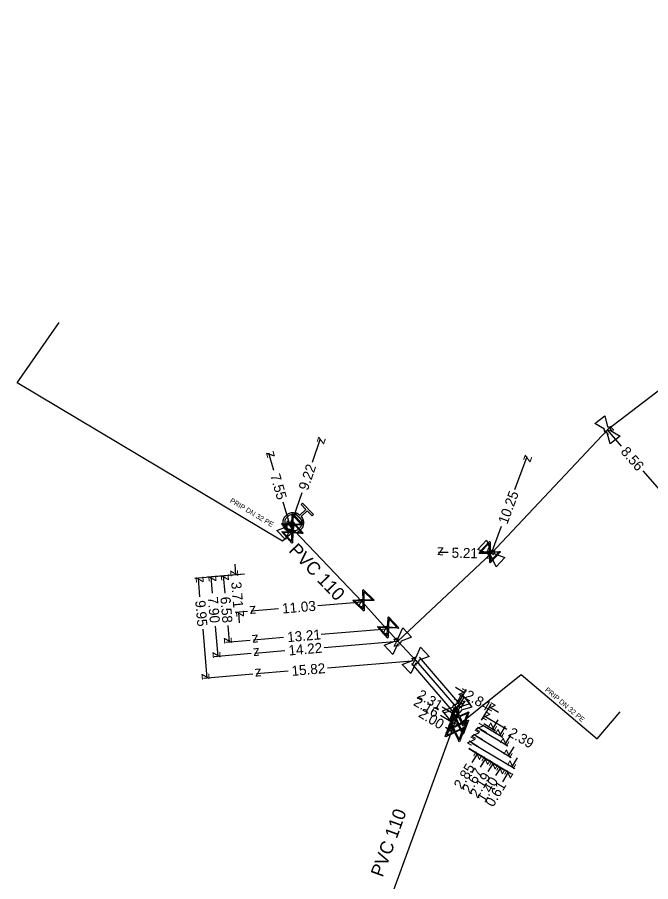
# Model space of a CAD drawing. Extents: x -638315 to -636370, y -1116147 to -1115110.
# Drawn here: x -637146.8 to -637084.1, y -1115729.6 to -1115644 of the extents above; entities that cross this region are included whole.
import ezdxf

# ---------------------------------------------------------------- set-up
doc = ezdxf.new("R2010")
doc.units = 0
for name, color, linetype in [('Default', 7, 'Continuous'), ('VP Chránička', 7, 'Continuous'), ('VP Hydrant', 7, 'Continuous'), ('VP Kótování', 7, 'Continuous'), ('VP Lomový bod', 7, 'Continuous'), ('VP Popis přípojky', 7, 'Continuous'), ('VP Přípojka', 7, 'Continuous'), ('VP Řad', 7, 'Continuous'), ('VP Řad - popis', 7, 'Continuous'), ('VP Šoupě', 7, 'Continuous')]:
    doc.layers.add(name, color=color, linetype=linetype)

msp = doc.modelspace()

# ---------------------------------------------------------------- linework, layer by layer
at = {"layer": 'Default'}
for points in [[(-637088.361, -1115684.546), (-637088.309, -1115684.55), (-637088.26, -1115684.571), (-637088.181, -1115684.606), (-637088.131, -1115684.671), (-637088.082, -1115684.736), (-637088.07, -1115684.819), (-637088.063, -1115684.873), (-637088.074, -1115684.925)], [(-637088.398, -1115685.172), (-637088.451, -1115685.169), (-637088.501, -1115685.148), (-637088.579, -1115685.115), (-637088.628, -1115685.05), (-637088.678, -1115684.985), (-637088.69, -1115684.898), (-637088.698, -1115684.846), (-637088.686, -1115684.794)], [(-637118.695, -1115693.44), (-637118.469, -1115693.72), (-637118.479, -1115694.086), (-637118.49, -1115694.499), (-637118.791, -1115694.786), (-637119.091, -1115695.071), (-637119.504, -1115695.061), (-637119.918, -1115695.05), (-637120.205, -1115694.749), (-637120.489, -1115694.451), (-637120.48, -1115694.037), (-637120.471, -1115693.624), (-637120.171, -1115693.338), (-637119.87, -1115693.051), (-637119.457, -1115693.059), (-637119.09, -1115693.065), (-637118.822, -1115693.307)], [(-637118.891, -1115693.497), (-637119.125, -1115693.252), (-637119.46, -1115693.244), (-637119.796, -1115693.236), (-637120.04, -1115693.47), (-637120.285, -1115693.703), (-637120.293, -1115694.038), (-637120.301, -1115694.374), (-637120.068, -1115694.618), (-637119.836, -1115694.861), (-637119.5, -1115694.87), (-637119.164, -1115694.879), (-637118.919, -1115694.646), (-637118.674, -1115694.413), (-637118.666, -1115694.077), (-637118.658, -1115693.742), (-637118.891, -1115693.497)], [(-637119.786, -1115694.043), (-637119.692, -1115694.043), (-637119.602, -1115694.091), (-637119.512, -1115694.14), (-637119.462, -1115694.23), (-637119.411, -1115694.32), (-637119.411, -1115694.418), (-637119.411, -1115694.516), (-637119.46, -1115694.605), (-637119.51, -1115694.694), (-637119.599, -1115694.744), (-637119.689, -1115694.793), (-637119.786, -1115694.793), (-637119.883, -1115694.793), (-637119.973, -1115694.744), (-637120.062, -1115694.694), (-637120.112, -1115694.605), (-637120.161, -1115694.516), (-637120.161, -1115694.418), (-637120.161, -1115694.32), (-637120.111, -1115694.23), (-637120.06, -1115694.14), (-637119.971, -1115694.091), (-637119.881, -1115694.043), (-637119.786, -1115694.043)], [(-637119.786, -1115694.09), (-637119.869, -1115694.09), (-637119.948, -1115694.132), (-637120.026, -1115694.174), (-637120.07, -1115694.253), (-637120.114, -1115694.332), (-637120.114, -1115694.418), (-637120.114, -1115694.504), (-637120.071, -1115694.582), (-637120.028, -1115694.659), (-637119.95, -1115694.703), (-637119.871, -1115694.746), (-637119.786, -1115694.746), (-637119.701, -1115694.746), (-637119.622, -1115694.703), (-637119.544, -1115694.659), (-637119.501, -1115694.582), (-637119.458, -1115694.504), (-637119.458, -1115694.418), (-637119.458, -1115694.332), (-637119.502, -1115694.253), (-637119.547, -1115694.174), (-637119.625, -1115694.132), (-637119.704, -1115694.09), (-637119.786, -1115694.09)], [(-637120.098, -1115694.434), (-637120.101, -1115694.381), (-637120.085, -1115694.329), (-637120.061, -1115694.249), (-637120.001, -1115694.192), (-637119.942, -1115694.136), (-637119.858, -1115694.114), (-637119.807, -1115694.101), (-637119.754, -1115694.106)], [(-637119.472, -1115694.402), (-637119.47, -1115694.454), (-637119.485, -1115694.506), (-637119.511, -1115694.588), (-637119.57, -1115694.644), (-637119.629, -1115694.701), (-637119.711, -1115694.721), (-637119.764, -1115694.735), (-637119.816, -1115694.729)], [(-637099.846, -1115697.423), (-637099.898, -1115697.429), (-637099.951, -1115697.416), (-637100.033, -1115697.396), (-637100.093, -1115697.34), (-637100.153, -1115697.284), (-637100.178, -1115697.201), (-637100.195, -1115697.151), (-637100.192, -1115697.098)], [(-637099.912, -1115696.8), (-637099.861, -1115696.795), (-637099.808, -1115696.807), (-637099.725, -1115696.828), (-637099.665, -1115696.884), (-637099.606, -1115696.94), (-637099.581, -1115697.021), (-637099.564, -1115697.073), (-637099.567, -1115697.126)], [(-637109.443, -1115705.802), (-637109.445, -1115705.749), (-637109.428, -1115705.697), (-637109.403, -1115705.617), (-637109.343, -1115705.561), (-637109.284, -1115705.505), (-637109.199, -1115705.485), (-637109.148, -1115705.472), (-637109.095, -1115705.478)], [(-637108.816, -1115705.777), (-637108.815, -1115705.829), (-637108.83, -1115705.881), (-637108.857, -1115705.962), (-637108.917, -1115706.018), (-637108.977, -1115706.074), (-637109.059, -1115706.094), (-637109.112, -1115706.106), (-637109.165, -1115706.1)], [(-637107.673, -1115707.702), (-637107.675, -1115707.649), (-637107.658, -1115707.597), (-637107.633, -1115707.517), (-637107.573, -1115707.461), (-637107.514, -1115707.405), (-637107.429, -1115707.385), (-637107.378, -1115707.372), (-637107.325, -1115707.378)], [(-637107.046, -1115707.677), (-637107.045, -1115707.729), (-637107.06, -1115707.781), (-637107.087, -1115707.862), (-637107.147, -1115707.918), (-637107.207, -1115707.974), (-637107.289, -1115707.994), (-637107.342, -1115708.006), (-637107.395, -1115708)], [(-637103.683, -1115712.339), (-637103.683, -1115712.286), (-637103.664, -1115712.235), (-637103.636, -1115712.156), (-637103.574, -1115712.102), (-637103.512, -1115712.049), (-637103.427, -1115712.032), (-637103.375, -1115712.022), (-637103.322, -1115712.03)], [(-637103.481, -1115712.583), (-637103.479, -1115712.53), (-637103.457, -1115712.48), (-637103.424, -1115712.402), (-637103.36, -1115712.352), (-637103.295, -1115712.303), (-637103.209, -1115712.29), (-637103.156, -1115712.282), (-637103.105, -1115712.294)], [(-637103.056, -1115712.34), (-637103.057, -1115712.392), (-637103.074, -1115712.443), (-637103.105, -1115712.524), (-637103.167, -1115712.577), (-637103.229, -1115712.63), (-637103.312, -1115712.646), (-637103.365, -1115712.657), (-637103.417, -1115712.649)], [(-637102.856, -1115712.618), (-637102.859, -1115712.67), (-637102.879, -1115712.719), (-637102.914, -1115712.798), (-637102.979, -1115712.848), (-637103.044, -1115712.898), (-637103.127, -1115712.91), (-637103.181, -1115712.917), (-637103.233, -1115712.906)]]:
    msp.add_open_spline(points, degree=3, dxfattribs=at)
at = {"layer": 'VP Chránička'}
for points in [[(-637102.99, -1115712.014), (-637106.98, -1115707.364)], [(-637103.749, -1115712.665), (-637107.739, -1115708.015)]]:
    msp.add_lwpolyline(points, dxfattribs=at)
at = {"layer": 'VP Hydrant'}
msp.add_lwpolyline([(-637118.822, -1115693.307), (-637118.228, -1115692.741), (-637118.704, -1115692.242), (-637118.571, -1115692.115), (-637117.493, -1115693.246), (-637117.626, -1115693.373), (-637118.102, -1115692.874), (-637118.695, -1115693.44)], dxfattribs=at)
at = {"layer": 'VP Kótování'}
for points in [[(-637086.987, -1115686.468), (-637088.38, -1115684.86)], [(-637117.587, -1115688.07), (-637116.77, -1115685.71)], [(-637121.397, -1115688.895), (-637121.9, -1115687.17)], [(-637097.535, -1115690.763), (-637096.33, -1115687.5)], [(-637084.864, -1115688.918), (-637082.776, -1115691.328)], [(-637118.637, -1115691.101), (-637119.786, -1115694.418)], [(-637120.498, -1115691.977), (-637119.786, -1115694.418)], [(-637098.889, -1115694.431), (-637099.879, -1115697.112)], [(-637104.156, -1115697.02), (-637105.09, -1115697)], [(-637101.124, -1115697.085), (-637099.879, -1115697.112)], [(-637125.281, -1115698.178), (-637125.193, -1115699.224)], [(-637124.319, -1115699.15), (-637129.224, -1115699.566)], [(-637128.717, -1115701.395), (-637128.875, -1115699.537)], [(-637124.319, -1115699.15), (-637127.968, -1115699.46)], [(-637127.482, -1115701.044), (-637127.619, -1115699.43)], [(-637124.319, -1115699.15), (-637126.728, -1115699.354)], [(-637126.234, -1115701.04), (-637126.379, -1115699.325)], [(-637124.319, -1115699.15), (-637125.541, -1115699.253)], [(-637117.042, -1115702.256), (-637112.669, -1115701.884)], [(-637124.005, -1115702.848), (-637125.227, -1115702.951)], [(-637124.79, -1115703.968), (-637124.879, -1115702.922)], [(-637120.937, -1115702.587), (-637123.656, -1115702.818)], [(-637125.962, -1115704.236), (-637125.822, -1115705.881)], [(-637128.446, -1115704.594), (-637128.033, -1115709.447)], [(-637127.205, -1115704.296), (-637126.95, -1115707.304)], [(-637116.714, -1115705.107), (-637110.247, -1115704.557)], [(-637123.762, -1115705.706), (-637126.171, -1115705.91)], [(-637120.434, -1115705.423), (-637123.413, -1115705.676)], [(-637116.408, -1115706.408), (-637109.13, -1115705.79)], [(-637120.302, -1115706.739), (-637123.301, -1115706.994)], [(-637123.65, -1115707.024), (-637127.299, -1115707.334)], [(-637116.108, -1115708.433), (-637107.36, -1115707.69)], [(-637123.477, -1115709.06), (-637128.382, -1115709.476)], [(-637120.002, -1115708.764), (-637123.128, -1115709.03)], [(-637103.423, -1115710.353), (-637102.517, -1115710.883)], [(-637103.193, -1115712.038), (-637102.34, -1115710.581)], [(-637103.562, -1115711.466), (-637102.656, -1115711.997)], [(-637102.902, -1115712.417), (-637102.479, -1115711.695)], [(-637104.748, -1115712.3), (-637103.247, -1115713.179)], [(-637100.746, -1115713.471), (-637099.893, -1115712.014)], [(-637099.164, -1115712.847), (-637100.07, -1115712.316)], [(-637104.919, -1115713.113), (-637103.522, -1115713.931)], [(-637100.837, -1115713.626), (-637100.414, -1115712.904)], [(-637098.336, -1115714.526), (-637100.591, -1115713.206)], [(-637099.216, -1115713.572), (-637099.756, -1115714.473)], [(-637104.417, -1115714.297), (-637103.793, -1115714.671)], [(-637100.351, -1115714.874), (-637101.257, -1115714.344)], [(-637100.957, -1115714.525), (-637098.237, -1115716.168)], [(-637100.714, -1115714.108), (-637098.739, -1115715.294)], [(-637100.623, -1115713.953), (-637099.456, -1115714.653)], [(-637098.499, -1115714.213), (-637099.039, -1115715.113)], [(-637100.749, -1115715.554), (-637101.655, -1115715.024)], [(-637101.357, -1115715.207), (-637097.914, -1115717.323)], [(-637097.994, -1115715.088), (-637098.537, -1115715.987)], [(-637101.177, -1115716.239), (-637102.078, -1115715.699)], [(-637101.778, -1115715.879), (-637097.553, -1115718.409)], [(-637102.092, -1115716.403), (-637098.649, -1115718.519)], [(-637102.09, -1115716.4), (-637100.923, -1115717.1)], [(-637102.09, -1115716.4), (-637097.865, -1115718.93)], [(-637102.09, -1115716.4), (-637100.115, -1115717.586)], [(-637102.09, -1115716.401), (-637099.37, -1115718.044)], [(-637101.761, -1115717.819), (-637101.223, -1115716.92)], [(-637097.662, -1115716.245), (-637098.212, -1115717.14)], [(-637100.937, -1115718.274), (-637100.415, -1115717.405)], [(-637100.178, -1115718.705), (-637099.67, -1115717.863)], [(-637097.314, -1115717.328), (-637097.854, -1115718.229)], [(-637099.417, -1115719.101), (-637098.947, -1115718.336)], [(-637098.747, -1115719.722), (-637098.166, -1115718.75)]]:
    msp.add_lwpolyline(points, dxfattribs=at)
at = {"layer": 'VP Lomový bod'}
for points in [[(-637089.635, -1115684.245), (-637088.641, -1115683.487), (-637088.361, -1115684.546)], [(-637088.686, -1115684.794), (-637089.635, -1115684.245)], [(-637088.074, -1115684.925), (-637087.125, -1115685.475), (-637088.119, -1115686.233), (-637088.398, -1115685.172)], [(-637119.754, -1115694.106), (-637119.312, -1115693.103)], [(-637119.312, -1115693.103), (-637118.45, -1115694.008), (-637119.472, -1115694.402)], [(-637119.816, -1115694.729), (-637120.259, -1115695.733), (-637121.122, -1115694.828), (-637120.098, -1115694.434)], [(-637101.218, -1115696.712), (-637100.363, -1115695.801), (-637099.912, -1115696.8)], [(-637100.192, -1115697.098), (-637101.218, -1115696.712)], [(-637099.567, -1115697.126), (-637098.54, -1115697.512), (-637099.395, -1115698.423), (-637099.846, -1115697.423)], [(-637109.095, -1115705.478), (-637108.642, -1115704.48)], [(-637108.642, -1115704.48), (-637107.79, -1115705.395), (-637108.816, -1115705.777)], [(-637109.165, -1115706.1), (-637109.619, -1115707.099), (-637110.471, -1115706.184), (-637109.443, -1115705.802)], [(-637107.325, -1115707.378), (-637106.872, -1115706.38)], [(-637106.872, -1115706.38), (-637106.02, -1115707.295), (-637107.046, -1115707.677)], [(-637107.395, -1115708), (-637107.849, -1115708.999), (-637108.701, -1115708.084), (-637107.673, -1115707.702)], [(-637103.322, -1115712.03), (-637102.829, -1115711.051)], [(-637102.829, -1115711.051), (-637102.015, -1115712), (-637103.056, -1115712.34)], [(-637103.105, -1115712.294), (-637102.558, -1115711.343)], [(-637102.558, -1115711.343), (-637101.797, -1115712.335), (-637102.856, -1115712.618)], [(-637103.417, -1115712.649), (-637103.912, -1115713.628), (-637104.726, -1115712.679), (-637103.683, -1115712.339)], [(-637103.233, -1115712.906), (-637103.78, -1115713.857), (-637104.541, -1115712.866), (-637103.481, -1115712.583)]]:
    msp.add_lwpolyline(points, dxfattribs=at)
at = {"layer": 'VP Přípojka'}
for points in [[(-637119.366, -1115694.856), (-637119.556, -1115695.026), (-637120.559, -1115695.868), (-637146.799, -1115680.212), (-637142.645, -1115674.222)], [(-637119.786, -1115694.418), (-637119.451, -1115694.088)], [(-637100.02, -1115696.97), (-637099.879, -1115697.112)], [(-637112.669, -1115701.884), (-637112.53, -1115701.74)], [(-637110.247, -1115704.557), (-637110.099, -1115704.423)], [(-637103.11, -1115714.07), (-637096.92, -1115709.095), (-637089.416, -1115715.469), (-637087.115, -1115712.799)], [(-637103.247, -1115713.179), (-637103.06, -1115713.25)], [(-637103.11, -1115714.07), (-637103.522, -1115713.931)], [(-637103.47, -1115714.78), (-637103.793, -1115714.671)]]:
    msp.add_lwpolyline(points, dxfattribs=at)
at = {"layer": 'VP Řad'}
for points in [[(-637033.449, -1115644.003), (-637034.72, -1115645.066), (-637037.433, -1115647.337), (-637039.97, -1115649.46), (-637049.002, -1115656.705), (-637049.937, -1115657.383), (-637056.219, -1115661.919), (-637056.264, -1115661.952), (-637072.516, -1115673.367), (-637078.87, -1115677.61), (-637088.38, -1115684.86), (-637099.879, -1115697.112), (-637109.13, -1115705.79)], [(-637119.786, -1115694.418), (-637119.366, -1115694.856), (-637112.669, -1115701.884), (-637110.247, -1115704.557), (-637109.13, -1115705.79)], [(-637109.13, -1115705.79), (-637107.36, -1115707.69), (-637103.37, -1115712.34), (-637103.079, -1115712.719), (-637103.247, -1115713.179), (-637110.19, -1115732.169), (-637110.57, -1115733.21), (-637110.92, -1115734.14)]]:
    msp.add_lwpolyline(points, dxfattribs=at)
at = {"layer": 'VP Šoupě'}
for points in [[(-637119.55, -1115693.149), (-637118.515, -1115694.235), (-637118.563, -1115694.281), (-637118.691, -1115694.273), (-637119.531, -1115694.254), (-637119.553, -1115695.225), (-637119.601, -1115695.27), (-637120.636, -1115694.184), (-637120.588, -1115694.139), (-637119.617, -1115694.164), (-637119.598, -1115693.324), (-637119.598, -1115693.195), (-637119.55, -1115693.149)], [(-637119.499, -1115693.967), (-637118.497, -1115695.084), (-637118.546, -1115695.128), (-637118.674, -1115695.117), (-637119.513, -1115695.072), (-637119.565, -1115696.041), (-637119.614, -1115696.085), (-637120.615, -1115694.968), (-637120.566, -1115694.924), (-637119.596, -1115694.979), (-637119.552, -1115694.14), (-637119.548, -1115694.011), (-637119.499, -1115693.967)], [(-637119.509, -1115693.328), (-637119.529, -1115694.166), (-637118.692, -1115694.185), (-637119.509, -1115693.328)], [(-637119.638, -1115695.095), (-637119.619, -1115694.252), (-637120.46, -1115694.233), (-637119.638, -1115695.095)], [(-637119.463, -1115694.147), (-637119.508, -1115694.984), (-637118.673, -1115695.028), (-637119.463, -1115694.147)], [(-637119.646, -1115695.909), (-637119.601, -1115695.067), (-637120.441, -1115695.022), (-637119.646, -1115695.909)], [(-637098.96, -1115696.937), (-637099.986, -1115698.031), (-637100.034, -1115697.985), (-637100.034, -1115697.857), (-637100.062, -1115697.017), (-637101.032, -1115697.049), (-637101.08, -1115697.004), (-637100.053, -1115695.91), (-637100.005, -1115695.955), (-637099.977, -1115696.927), (-637099.137, -1115696.899), (-637099.008, -1115696.892), (-637098.96, -1115696.937)], [(-637100.907, -1115696.957), (-637100.065, -1115696.929), (-637100.092, -1115696.089), (-637100.907, -1115696.957)], [(-637099.136, -1115696.987), (-637099.974, -1115697.015), (-637099.946, -1115697.851), (-637099.136, -1115696.987)], [(-637112.549, -1115700.68), (-637111.47, -1115701.721), (-637111.516, -1115701.769), (-637111.644, -1115701.767), (-637112.484, -1115701.783), (-637112.466, -1115702.753), (-637112.512, -1115702.801), (-637113.591, -1115701.759), (-637113.545, -1115701.711), (-637112.574, -1115701.696), (-637112.59, -1115700.856), (-637112.595, -1115700.727), (-637112.549, -1115700.68)], [(-637112.501, -1115700.856), (-637112.486, -1115701.695), (-637111.649, -1115701.679), (-637112.501, -1115700.856)], [(-637112.556, -1115702.627), (-637112.572, -1115701.784), (-637113.413, -1115701.8), (-637112.556, -1115702.627)], [(-637110.047, -1115703.363), (-637109.039, -1115704.475), (-637109.088, -1115704.519), (-637109.216, -1115704.509), (-637110.055, -1115704.468), (-637110.102, -1115705.438), (-637110.151, -1115705.482), (-637111.158, -1115704.37), (-637111.109, -1115704.326), (-637110.139, -1115704.376), (-637110.099, -1115703.537), (-637110.095, -1115703.408), (-637110.047, -1115703.363)], [(-637110.01, -1115703.543), (-637110.051, -1115704.38), (-637109.215, -1115704.421), (-637110.01, -1115703.543)], [(-637110.184, -1115705.306), (-637110.143, -1115704.464), (-637110.983, -1115704.424), (-637110.184, -1115705.306)], [(-637102.098, -1115712.803), (-637102.613, -1115714.212), (-637102.675, -1115714.189), (-637102.725, -1115714.071), (-637103.08, -1115713.31), (-637103.96, -1115713.72), (-637104.022, -1115713.697), (-637103.507, -1115712.288), (-637103.445, -1115712.311), (-637103.038, -1115713.193), (-637102.276, -1115712.838), (-637102.16, -1115712.781), (-637102.098, -1115712.803)], [(-637103.882, -1115713.586), (-637103.117, -1115713.23), (-637103.473, -1115712.468), (-637103.882, -1115713.586)], [(-637102.148, -1115713.623), (-637102.663, -1115715.032), (-637102.725, -1115715.009), (-637102.775, -1115714.891), (-637103.13, -1115714.13), (-637104.01, -1115714.54), (-637104.072, -1115714.517), (-637103.557, -1115713.108), (-637103.495, -1115713.131), (-637103.088, -1115714.013), (-637102.326, -1115713.658), (-637102.21, -1115713.601), (-637102.148, -1115713.623)], [(-637103.932, -1115714.406), (-637103.167, -1115714.05), (-637103.523, -1115713.288), (-637103.932, -1115714.406)], [(-637102.24, -1115712.919), (-637103, -1115713.273), (-637102.647, -1115714.031), (-637102.24, -1115712.919)], [(-637102.508, -1115714.333), (-637103.023, -1115715.742), (-637103.085, -1115715.719), (-637103.135, -1115715.601), (-637103.49, -1115714.84), (-637104.37, -1115715.25), (-637104.432, -1115715.227), (-637103.917, -1115713.818), (-637103.855, -1115713.841), (-637103.448, -1115714.723), (-637102.686, -1115714.368), (-637102.57, -1115714.311), (-637102.508, -1115714.333)], [(-637104.292, -1115715.116), (-637103.527, -1115714.76), (-637103.883, -1115713.998), (-637104.292, -1115715.116)], [(-637102.65, -1115714.449), (-637103.41, -1115714.803), (-637103.057, -1115715.561), (-637102.65, -1115714.449)], [(-637102.29, -1115713.739), (-637103.05, -1115714.093), (-637102.697, -1115714.851), (-637102.29, -1115713.739)]]:
    msp.add_lwpolyline(points, dxfattribs=at)

# ---------------------------------------------------------------- texts
at = {"layer": 'VP Kótování'}
for s, rotation, p in [('z', 130.9063, (-637087.675, -1115684.91)), ('z', 70.89654, (-637116.461, -1115686.346)), ('z', 106.26018, (-637121.28, -1115687.51)), ('8.56', 310.90627, (-637087.135, -1115687.06)), ('z', 69.73452, (-637096.034, -1115688.142)), ('9.22', 70.89654, (-637118.05, -1115690.934)), ('7.55', 286.2602, (-637121.779, -1115689.371)), ('10.25', 69.73452, (-637098.299, -1115694.276)), ('z', 286.26022, (-637120.406, -1115694.078)), ('z', 250.89657, (-637120.095, -1115693.782)), ('z', 178.76873, (-637104.579, -1115696.511)), ('5.21', 358.76875, (-637103.817, -1115697.527)), ('z', 249.73456, (-637100.175, -1115696.47)), ('z', 358.76871, (-637100.39, -1115697.601)), ('z', 274.85337, (-637125.733, -1115698.768)), ('z', 94.85643, (-637128.335, -1115699.993)), ('z', 94.85637, (-637127.078, -1115699.886)), ('z', 94.8562, (-637125.839, -1115699.781)), ('3.71', 274.85341, (-637125.633, -1115699.946)), ('7.90', 274.85639, (-637127.95, -1115701.435)), ('6.58', 274.85622, (-637126.702, -1115701.431)), ('z', 4.85903, (-637113.125, -1115702.425)), ('9.95', 274.85645, (-637129.186, -1115701.786)), ('z', 184.85901, (-637123.2, -1115702.277)), ('11.03', 4.85903, (-637120.545, -1115703.055)), ('z', 94.85339, (-637124.338, -1115703.378)), ('13.21', 4.85799, (-637120.043, -1115705.891)), ('z', 4.85799, (-637110.703, -1115705.098)), ('z', 274.85618, (-637126.363, -1115705.425)), ('z', 184.85797, (-637122.957, -1115705.135)), ('14.22', 4.85633, (-637119.911, -1115707.208)), ('z', 4.85633, (-637109.586, -1115706.331)), ('z', 184.85631, (-637122.845, -1115706.453)), ('z', 274.85635, (-637127.49, -1115706.848)), ('z', 4.85748, (-637107.816, -1115708.231)), ('z', 184.85746, (-637122.672, -1115708.489)), ('15.82', 4.85748, (-637119.611, -1115709.233)), ('z', 274.85647, (-637128.574, -1115708.991)), ('2.31', 329.65413, (-637107.316, -1115711.376)), ('z', 329.64613, (-637103.201, -1115711.062)), ('2.84', 329.64611, (-637102.599, -1115711.415)), ('2.16', 329.65396, (-637107.667, -1115712.084)), ('z', 329.6522, (-637103.34, -1115712.176)), ('z', 149.64609, (-637099.386, -1115712.138)), ('2.00', 329.06083, (-637107.173, -1115713.228)), ('z', 329.65415, (-637103.931, -1115713.358)), ('z', 149.65222, (-637099.907, -1115713.027)), ('z', 329.65398, (-637104.206, -1115714.11)), ('z', 329.06079, (-637104.479, -1115714.843)), ('z', 149.65411, (-637100.573, -1115714.165)), ('z', 239.05692, (-637099.927, -1115713.787)), ('z', 239.02157, (-637099.211, -1115714.427)), ('2.39', 329.65224, (-637098.286, -1115715.135)), ('z', 149.06081, (-637101.392, -1115715.527)), ('z', 149.65394, (-637100.971, -1115714.845)), ('z', 238.87036, (-637098.706, -1115715.3)), ('z', 59.05688, (-637101.051, -1115717.606)), ('z', 238.42724, (-637098.376, -1115716.452)), ('2.85', 59.05688, (-637102.803, -1115720.529)), ('z', 59.02153, (-637100.244, -1115718.091)), ('z', 58.87032, (-637099.5, -1115718.549)), ('z', 239.08476, (-637098.026, -1115717.543)), ('2.67', 59.02153, (-637101.979, -1115720.982)), ('z', 58.42726, (-637098.783, -1115719.024)), ('z', 59.08478, (-637097.993, -1115719.436)), ('2.19', 58.87032, (-637101.228, -1115721.41)), ('1.40', 58.42726, (-637100.517, -1115721.845)), ('0.61', 59.08478, (-637099.697, -1115722.281))]:
    msp.add_text(s, height=1, rotation=rotation, dxfattribs=at).set_placement(p)
at = {"layer": 'VP Popis přípojky'}
for rotation, p in [(329.17674, (-637125.802, -1115692.013)), (319.65499, (-637094.614, -1115710.688))]:
    msp.add_text('PRIP DN 32 PE', height=0.5, rotation=rotation, dxfattribs=at).set_placement(p)
at = {"layer": 'VP Řad - popis'}
for rotation, p in [(313.62908, (-637119.998, -1115696.86)), (69.91884, (-637110.639, -1115729.233))]:
    msp.add_text('PVC 110', height=1.3, rotation=rotation, dxfattribs=at).set_placement(p)

doc.saveas('drawing.dxf')
